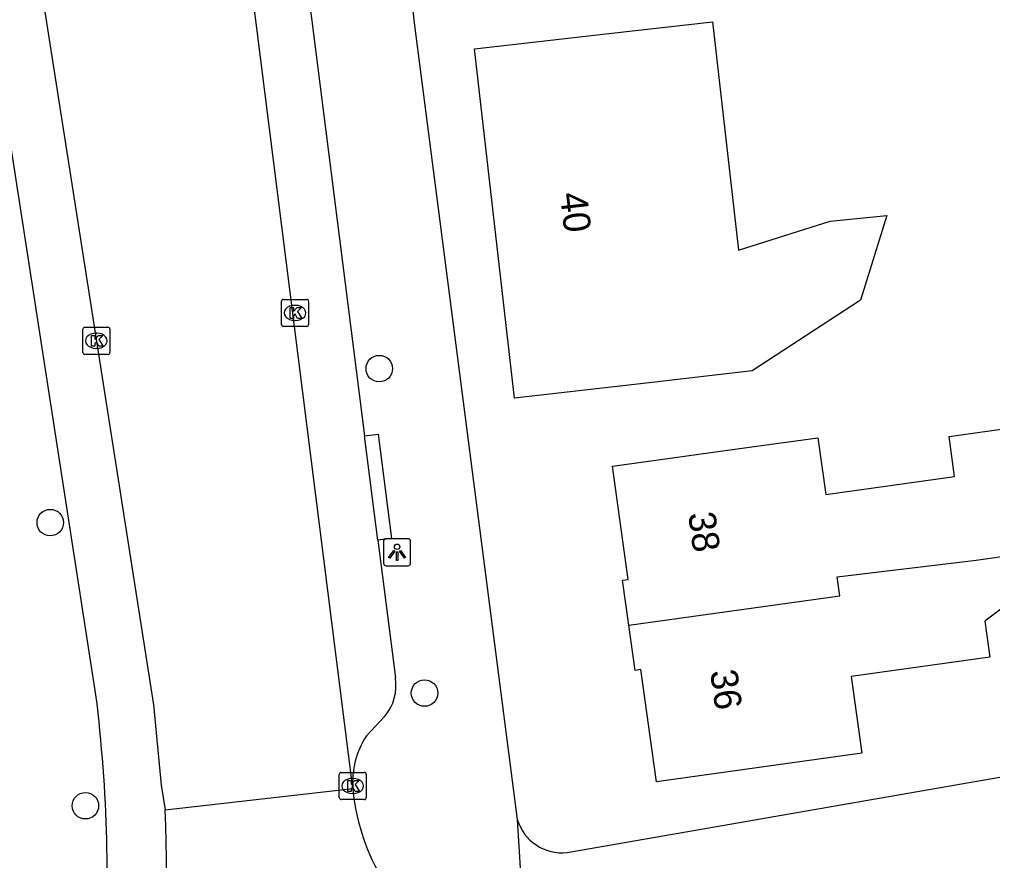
# Model space of a CAD drawing. Extents: x 162880 to 165536, y 384011 to 385179.
# Drawn here: x 164280.76 to 164316.65, y 384410.47 to 384441.49 of the extents above; entities that cross this region are included whole.
import ezdxf

# ---------------------------------------------------------------- set-up
doc = ezdxf.new("R2010")
doc.units = 0
for name, color, linetype in [('IMGEO_Boom', 7, 'Continuous'), ('IMGEO_Kolk', 7, 'Continuous'), ('IMGEO_Lichtpunt', 7, 'Continuous'), ('IMGEO_Pand', 7, 'Continuous'), ('IMGEO_Pand_nummerreeks', 7, 'Continuous'), ('IMGEO_Rijbaan_lokaal_gesloten', 7, 'Continuous'), ('IMGEO_Voetpad_open', 7, 'Continuous')]:
    doc.layers.add(name, color=color, linetype=linetype)

msp = doc.modelspace()

# ---------------------------------------------------------------- linework, layer by layer
at = {"layer": 'IMGEO_Boom'}
for centre in [(164294.031, 384428.615), (164281.896, 384422.936), (164295.701, 384416.653), (164283.191, 384412.496)]:
    msp.add_circle(centre, 0.489, dxfattribs=at)
at = {"layer": 'IMGEO_Kolk'}
for p, q in [((164290.423, 384430.244), (164290.423, 384431.096)), ((164290.498, 384431.17), (164291.35, 384431.17)), ((164290.911, 384430.95), (164290.936, 384430.95)), ((164291.424, 384431.096), (164291.424, 384430.244)), ((164290.934, 384430.39), (164290.909, 384430.39)), ((164283.097, 384429.216), (164283.097, 384430.068)), ((164283.172, 384430.142), (164284.024, 384430.142)), ((164283.585, 384429.922), (164283.61, 384429.922)), ((164284.098, 384430.068), (164284.098, 384429.216)), ((164291.35, 384430.17), (164290.498, 384430.17)), ((164284.024, 384429.142), (164283.172, 384429.142)), ((164283.608, 384429.362), (164283.583, 384429.362)), ((164292.626, 384413.724), (164293.478, 384413.724)), ((164292.551, 384412.798), (164292.551, 384413.65)), ((164293.039, 384413.504), (164293.064, 384413.504)), ((164293.552, 384413.65), (164293.552, 384412.798)), ((164293.478, 384412.724), (164292.626, 384412.724)), ((164293.062, 384412.944), (164293.037, 384412.944))]:
    msp.add_line(p, q, dxfattribs=at)
for points in [[(164290.423, 384430.244), (164290.423, 384431.096)], [(164290.498, 384431.17), (164291.35, 384431.17)], [(164291.424, 384431.096), (164291.424, 384430.244)], [(164290.744, 384430.87), (164290.867, 384430.87), (164290.867, 384430.719), (164290.997, 384430.87), (164291.161, 384430.87), (164291.015, 384430.719), (164291.168, 384430.47), (164291.016, 384430.47), (164290.931, 384430.634), (164290.867, 384430.567), (164290.867, 384430.47), (164290.744, 384430.47), (164290.744, 384430.87)], [(164283.097, 384429.216), (164283.097, 384430.068)], [(164283.172, 384430.142), (164284.024, 384430.142)], [(164283.418, 384429.842), (164283.541, 384429.842), (164283.541, 384429.691), (164283.671, 384429.842), (164283.835, 384429.842), (164283.689, 384429.691), (164283.842, 384429.442), (164283.69, 384429.442), (164283.605, 384429.606), (164283.541, 384429.539), (164283.541, 384429.442), (164283.418, 384429.442), (164283.418, 384429.842)], [(164284.098, 384430.068), (164284.098, 384429.216)], [(164291.35, 384430.17), (164290.498, 384430.17)], [(164284.024, 384429.142), (164283.172, 384429.142)], [(164292.626, 384413.724), (164293.478, 384413.724)], [(164292.551, 384412.798), (164292.551, 384413.65)], [(164292.872, 384413.424), (164292.995, 384413.424), (164292.995, 384413.273), (164293.125, 384413.424), (164293.289, 384413.424), (164293.143, 384413.273), (164293.296, 384413.024), (164293.144, 384413.024), (164293.059, 384413.188), (164292.995, 384413.121), (164292.995, 384413.024), (164292.872, 384413.024), (164292.872, 384413.424)], [(164293.552, 384413.65), (164293.552, 384412.798)], [(164293.478, 384412.724), (164292.626, 384412.724)]]:
    msp.add_lwpolyline(points, dxfattribs=at)
for centre, start, end in [((164290.5, 384431.094), 91.552, 178.448), ((164290.5, 384431.094), 91.552, 178.448), ((164291.348, 384431.094), 1.552, 88.448), ((164291.348, 384431.094), 1.552, 88.448), ((164290.5, 384430.246), 181.552, 268.448), ((164290.5, 384430.246), 181.552, 268.448), ((164291.348, 384430.246), 271.552, 358.448), ((164291.348, 384430.246), 271.552, 358.448), ((164283.174, 384430.066), 91.552, 178.448), ((164283.174, 384430.066), 91.552, 178.448), ((164284.022, 384430.066), 1.552, 88.448), ((164284.022, 384430.066), 1.552, 88.448), ((164283.174, 384429.218), 181.552, 268.448), ((164283.174, 384429.218), 181.552, 268.448), ((164284.022, 384429.218), 271.552, 358.448), ((164284.022, 384429.218), 271.552, 358.448), ((164292.628, 384413.648), 91.552, 178.448), ((164292.628, 384413.648), 91.552, 178.448), ((164293.476, 384413.648), 1.552, 88.448), ((164293.476, 384413.648), 1.552, 88.448), ((164292.628, 384412.8), 181.552, 268.448), ((164292.628, 384412.8), 181.552, 268.448), ((164293.476, 384412.8), 271.552, 358.448), ((164293.476, 384412.8), 271.552, 358.448)]:
    msp.add_arc(centre, 0.0765, start, end, dxfattribs=at)
for centre, major_axis, ratio, start_param, end_param in [((164290.91, 384430.67), (-0.387, 0.002), 0.722429, 4.712389, 7.853982), ((164290.935, 384430.67), (-0.39, 0.002), 0.717154, 1.570796, 4.712389), ((164283.584, 384429.642), (-0.387, 0.002), 0.722429, 4.712389, 7.853982), ((164283.609, 384429.642), (-0.39, 0.002), 0.717154, 1.570796, 4.712389), ((164293.038, 384413.224), (-0.387, 0.002), 0.722429, 4.712389, 7.853982), ((164293.063, 384413.224), (-0.39, 0.002), 0.717154, 1.570796, 4.712389)]:
    msp.add_ellipse(centre, major_axis=major_axis, ratio=ratio, start_param=start_param, end_param=end_param, dxfattribs=at)
at = {"layer": 'IMGEO_Lichtpunt'}
for p, q in [((164295.091, 384422.343), (164294.283, 384422.343)), ((164295.091, 384422.343), (164294.283, 384422.343)), ((164294.189, 384422.248), (164294.189, 384421.441)), ((164294.189, 384422.248), (164294.189, 384421.441)), ((164295.185, 384421.441), (164295.185, 384422.248)), ((164295.185, 384421.441), (164295.185, 384422.248)), ((164294.283, 384421.347), (164295.091, 384421.347)), ((164294.283, 384421.347), (164295.091, 384421.347))]:
    msp.add_line(p, q, dxfattribs=at)
for points in [[(164294.563, 384421.912), (164294.602, 384421.884), (164294.414, 384421.622), (164294.376, 384421.649), (164294.563, 384421.912)], [(164294.665, 384421.864), (164294.712, 384421.864), (164294.712, 384421.542), (164294.665, 384421.542), (164294.665, 384421.864)], [(164294.775, 384421.884), (164294.813, 384421.911), (164295, 384421.649), (164294.961, 384421.621), (164294.775, 384421.884)]]:
    msp.add_lwpolyline(points, dxfattribs=at)
msp.add_circle((164294.688, 384422.046), 0.0994, dxfattribs=at)
for centre, start, end in [((164294.283, 384422.248), 90, 180), ((164294.283, 384422.248), 90, 180), ((164295.091, 384422.248), 0, 90), ((164295.091, 384422.248), 0, 90), ((164294.283, 384421.441), 180, 270), ((164294.283, 384421.441), 180, 270), ((164295.091, 384421.441), 270, 0), ((164295.091, 384421.441), 270, 360)]:
    msp.add_arc(centre, 0.0946, start, end, dxfattribs=at)
at = {"layer": 'IMGEO_Pand'}
for points in [[(164306.318, 384441.407), (164307.28, 384432.979), (164310.657, 384434.051), (164312.755, 384434.266), (164311.775, 384431.142), (164307.788, 384428.531), (164303.984, 384428.097), (164299.016, 384427.53), (164297.546, 384440.404), (164302.493, 384440.97), (164306.318, 384441.407)], [(164303.237, 384419.15), (164303.005, 384420.817), (164303.209, 384420.845), (164302.629, 384425.016), (164307.582, 384425.704), (164310.205, 384426.068), (164310.496, 384423.975), (164315.251, 384424.636), (164315.045, 384426.116), (164319.244, 384426.699), (164319.629, 384423.92)], [(164319.629, 384423.92), (164321.304, 384424.152), (164321.752, 384420.931), (164317.8, 384420.382), (164316.36, 384419.299), (164316.544, 384417.971), (164311.435, 384417.261), (164311.828, 384414.431), (164304.251, 384413.379), (164303.677, 384417.514), (164303.468, 384417.485), (164303.237, 384419.15)], [(164303.237, 384419.15), (164311.02, 384420.236), (164310.922, 384420.935), (164316.045, 384421.555), (164317.58, 384421.77), (164317.325, 384423.6), (164319.629, 384423.92)]]:
    msp.add_lwpolyline(points, dxfattribs=at)
at = {"layer": 'IMGEO_Rijbaan_lokaal_gesloten'}
for points in [[(164293.057, 384413.129), (164283.658, 384487.529)], [(164275.161, 384483.409), (164285.705, 384416.219), (164285.992, 384413.26), (164286.139, 384412.339)], [(164286.139, 384412.339), (164293.057, 384413.129)], [(164293.057, 384413.129), (164293.065, 384412.976)]]:
    msp.add_lwpolyline(points, dxfattribs=at)
for centre, radius, start, end in [((164301.014, 384413.89), 8.001, 186.561, 236.0646), ((164214.239, 384409.661), 71.95, 347.05753, 2.13317)]:
    msp.add_arc(centre, radius, start, end, dxfattribs=at)
at = {"layer": 'IMGEO_Voetpad_open'}
for points in [[(164285.786, 384518.69), (164283.972, 384516.463), (164283.48, 384513.165), (164284.083, 384509.933), (164286.485, 384500), (164287.479, 384494.408), (164289.825, 384479.842), (164292.496, 384465.91), (164295.335, 384441.27), (164299.12, 384411.99)], [(164283.582, 384416.585), (164276.24, 384463.966)], [(164291.045, 384445.426), (164293.491, 384426.14)], [(164293.491, 384426.14), (164293.987, 384426.202), (164294.476, 384422.348), (164293.98, 384422.286)], [(164293.98, 384422.286), (164293.491, 384426.14)], [(164293.98, 384422.286), (164294.624, 384417.207)], [(164294.237, 384415.797), (164293.555, 384415.07)], [(164300.956, 384410.768), (164327.581, 384415.411)], [(164299.12, 384411.99), (164299.489, 384406.036)]]:
    msp.add_lwpolyline(points, dxfattribs=at)
for centre, radius, start, end in [((164292.888, 384416.925), 1.759, 320.0906, 9.2136), ((164228.44, 384409.799), 55.558, 355.9763, 7.0154), ((164296.167, 384413.365), 3.119, 146.8741, 184.3461), ((164300.774, 384412.485), 1.726, 196.6566, 276.0497)]:
    msp.add_arc(centre, radius, start, end, dxfattribs=at)

# ---------------------------------------------------------------- texts
at = {"layer": 'IMGEO_Pand_nummerreeks'}
for s, rotation, p in [('40', 276.5143, (164300.692, 384435.07)), ('38', 277.9353, (164305.417, 384423.27)), ('36', 277.9353, (164306.228, 384417.455))]:
    msp.add_text(s, height=1, rotation=rotation, dxfattribs=at).set_placement(p)

doc.saveas('drawing.dxf')
